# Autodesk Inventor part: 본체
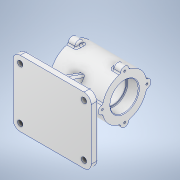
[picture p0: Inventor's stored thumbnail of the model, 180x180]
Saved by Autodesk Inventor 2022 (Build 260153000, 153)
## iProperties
Created: 2023-05
Part Number: 본체
Material: 알루미늄 6061
Document SubType Name: Modeling
Designer: Admin
Density: 2.7 g/cm^3
Appearance: 알루미늄 - 평지
Mass: 1214.64 g
Surface Area: 798.693 cm^2
Volume: 449.868 cm^3
Author: Admin
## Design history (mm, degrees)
sketch "스케치1"
  geometry: L1 (-91, 0)-(91, 0) reference; L2 (0, -77)-(0, 77) reference; L3 (65, -55)-(-65, -55); L4 (-65, -55)-(-65, 55); L5 (-65, 55)-(65, 55); L6 (65, 55)-(65, -55); L7 (65, -55)-(-65, 55); L8 (-65, -55)-(65, 55); 1 further point
  constraints: 12 end point, 2 midpoint, 2 parallel, 1 horizontal, 1 perpendicular
  dimensions: "d0" = 130 distance of L4.end L5.end; "d1" = 110 distance of L5.end L3.start
extrude "돌출1" new body sketch "스케치1" distance "d2" = 12; taper "d3" = 0 deg
fillet "모깎기1" dims "d8" = 12
sketch "스케치3"
  geometry: L1 (93.982, 0)-(-91.497, 0) reference; L2 (0, -77.497)-(0, 79.982) reference; C1 r 4.5 at (53, 43); C2 r 4.5 at (53, -43); C3 r 4.5 at (-53, 43); C4 r 4.5 at (-53, -43); A1 r 12 centre (53, 43) between (65, 43) and (53, 55) reference; 1 further point
  constraints: 4 centre point, 3 symmetric about line, 1 coincident, 3 other
  dimensions: "d9" = 9 diameter of C1
extrude "돌출3" cut sketch "스케치3" stored distance "d10" = 87; taper "d11" = 0 deg
node "작업 평면1"
sketch "스케치5"
  geometry: L1 (0, -2.4)-(0, 14.4) reference; L2 (-77, 0)-(77, 0) reference; L3 (-43, 12)-(43, 12) reference; C1 r 37 at (0, -70); 1 further point
  constraints: 1 centre point, 1 point on line
  dimensions: "d14" = 82 distance from line of L3 C1.centre; "d15" = 74 diameter of C1
extrude "돌출4" join sketch "스케치5" stored distance "d16" = 87; taper "d17" = 0 deg
sketch "스케치6"
  geometry: L1 (0, -77)-(0, 77) reference; L2 (0, 41)-(10, 41); L3 (10, 41)-(10, -41); L4 (10, -41)-(0, -41); L5 (0, -41)-(0, 41); L6 (0, 41)-(10, -41); L7 (10, 41)-(0, -41); L8 (-65, -43)-(-65, 43) reference; L9 (-15, 5)-(25, 5); L10 (25, 5)-(25, -5); L11 (25, -5)-(-15, -5); L12 (-15, -5)-(-15, 5); L13 (-15, 5)-(25, -5); L14 (25, 5)-(-15, -5); L15 (91, 0)-(-91, 0) reference; L16 (53, -55)-(-53, -55) reference; L17 (-53, 55)-(53, 55) reference; 6 further points
  constraints: 24 end point, 4 midpoint, 4 parallel, 2 horizontal, 2 perpendicular, 1 point on line
  dimensions: "d18" = 70 distance from line of L8 point (5, 0); "d19" = 10 distance of L2.start L2.end; "d20" = 10 distance of L9.end L10.end; "d21" = 40 distance of L10.end L11.end; "d84" = 14 distance between parallel lines of L17 L2
extrude "돌출5" join sketch "스케치6" distance "d23" = 82; taper "d24" = 0 deg
feature "면 기울기1" dims angle "d25" = 20 deg
feature "면 기울기2" dims angle "d26" = 20 deg
sketch "스케치7"
  geometry: L1 (68.733, 0)-(-107.122, 0) reference; C1 r 7 at (37, 0); C2 r 7 at (0, 37); C3 r 7 at (-37, 0); C4 r 7 at (0, -37); 10 further points
  constraints: 4 centre point, 1 point on line, 11 other
  dimensions: "d27" = 14 diameter of C1; "d30" = 360 deg dimension on point (0, 0) C1.centre (derived)
extrude "돌출6" join sketch "스케치7" distance "d32" = 14; taper "d33" = 0 deg
sketch "스케치8"
  geometry: L1 (-69.2, 0)-(107.2, 0) reference; C1 r 7 at (-37, 0); C2 r 7 at (0, -37); C3 r 7 at (37, 0); C4 r 7 at (0, 37); A1 r 7 centre (-37, 0) between (-36.338, 6.969) and (-36.338, -6.969) reference; A2 r 37 centre (0, 0) between (-36.338, -6.969) and (-36.338, 6.969) reference; 3 further points
  constraints: 4 centre point, 1 coincident, 9 other
  dimensions: "d34" = 14 diameter of C1; "d37" = 360 deg dimension on A2.centre C1.centre (derived)
extrude "돌출7" join sketch "스케치8" distance "d39" = 14; taper "d40" = 0 deg
sketch "스케치9"
  geometry: A1 r 7 centre (107, 0) between (106.338, -6.969) and (106.338, 6.969) reference; A2 r 37 centre (70, 0) between (106.338, 6.969) and (76.969, 36.338) reference; A3 r 37 centre (70, 0) between (63.031, 36.338) and (33.662, 6.969) reference; A4 r 7 centre (33, 0) between (33.662, 6.969) and (33.662, -6.969) reference; A5 r 37 centre (70, 0) between (33.662, -6.969) and (63.031, -36.338) reference; A6 r 7 centre (70, -37) between (63.031, -36.338) and (76.969, -36.338) reference; A7 r 37 centre (70, 0) between (76.969, -36.338) and (106.338, -6.969) reference; A8 r 7 centre (107, 0) between (106.338, -6.969) and (106.338, 6.969) reference; A9 r 37 centre (70, 0) between (106.338, 6.969) and (76.969, 36.338) reference; A10 r 7 centre (70, 37) between (76.969, 36.338) and (63.031, 36.338) reference; A11 r 7 centre (70, -37) between (63.031, -36.338) and (76.969, -36.338) reference; 5 further points
  constraints: 4 coincident
hole "구멍1" sketch "스케치9" at (107, 0), (70, 37), (33, 0), (70, -37) diameter "d45" = 3.242; stored, may be unused: countersink angle "d49" = 82 deg, drill point angle "d51" = 118 deg; dims "d46" = 8, "d47" = 3.023, "d48" = 2, "d50" = 10
sketch "스케치10"
  geometry: C1 r 1.621 at (-107, 0) reference; C2 r 1.621 at (-33, 0) reference; A1 r 37 centre (-70, 0) between (-76.969, 36.338) and (-106.338, 6.969) reference; A2 r 37 centre (-70, 0) between (-33.662, 6.969) and (-63.031, 36.338) reference; A3 r 7 centre (-70, 37) between (-63.031, 36.338) and (-76.969, 36.338) reference; A4 r 37 centre (-70, 0) between (-76.969, 36.338) and (-106.338, 6.969) reference; A5 r 7 centre (-107, 0) between (-106.338, 6.969) and (-106.338, -6.969) reference; A6 r 37 centre (-70, 0) between (-106.338, -6.969) and (-76.969, -36.338) reference; A7 r 7 centre (-70, -37) between (-76.969, -36.338) and (-63.031, -36.338) reference; A8 r 37 centre (-70, 0) between (-63.031, -36.338) and (-33.662, -6.969) reference; A9 r 7 centre (-33, 0) between (-33.662, -6.969) and (-33.662, 6.969) reference; 5 further points
  constraints: 4 coincident
hole "구멍2" sketch "스케치10" at (-70, 37), (-107, 0), (-70, -37), (-33, 0) diameter "d52" = 3.242; stored, may be unused: countersink angle "d56" = 90 deg, drill point angle "d58" = 118 deg; dims "d53" = 8, "d54" = 4, "d55" = 2, "d57" = 10
fillet "모깎기6" dims "d59" = 3
sketch "스케치11"
  geometry: L1 (-139.2, 0)-(37.2, 0) reference; C1 r 23.5 at (-70, 0); A1 r 37 centre (-70, 0) between (-33.662, 6.969) and (-63.031, 36.338) reference; 1 further point
  constraints: 1 centre point, 1 concentric, 1 point on line
  dimensions: "d60" = 47 diameter of C1
extrude "돌출8" cut sketch "스케치11" distance "d61" = 19; taper "d62" = 0 deg
sketch "스케치12"
  geometry: C1 r 21 at (0, 0); A1 r 37 centre (0, 0) between (36.338, 6.969) and (6.969, 36.338) reference; 1 further point
  constraints: 1 centre point, 1 concentric
  dimensions: "d63" = 42 diameter of C1
extrude "돌출9" cut sketch "스케치12" distance "d64" = 49; taper "d65" = 0 deg
sketch "스케치13"
  geometry: C1 r 23.5 at (70, 0); A1 r 37 centre (70, 0) between (106.338, 6.969) and (76.969, 36.338) reference; 1 further point
  constraints: 1 centre point, 1 coincident
  dimensions: "d66" = 47 diameter of C1
extrude "돌출10" cut sketch "스케치13" distance "d67" = 19; taper "d68" = 0 deg
chamfer "모따기1" distance "d69" = 1; stored, may be unused: second distance "d70" = 2, angle "d71" = 45 deg
sketch "스케치14"
  geometry: L1 (0, 41)-(10, 41) reference; L2 (5, 41)-(5, -41); L3 (10, -41)-(0, -41) reference; 2 further points
  constraints: 2 end point, 2 midpoint, 1 horizontal alignment, 1 other
  dimensions: "d73" = 58 distance from line of L2 point (-53, 0)
feature "엠보싱1" sketch "스케치14" dims "d74" = 0.5, "d75" = 0
fillet "모깎기7" dims "d76" = 3
fillet "모깎기8" dims "d77" = 3
fillet "모깎기9" dims "d78" = 1
fillet "모깎기10" dims "d79" = 3
fillet "모깎기11" dims "d80" = 3
fillet "모깎기12" dims "d81" = 3
fillet "모깎기13" dims "d82" = 3
node "솔리드1"
node "투영된 루프1"
node "투영된 루프2"
feature "A9D066F2-1C7D-4E18-AEED-F7BC21143FA4" dims "d45" = 3.242, "d46" = 8, "d47" = 3.023, "d48" = 2, "d49" = 82 deg, "d50" = 10, "d51" = 118 deg
other parameters: "d13" = -5
